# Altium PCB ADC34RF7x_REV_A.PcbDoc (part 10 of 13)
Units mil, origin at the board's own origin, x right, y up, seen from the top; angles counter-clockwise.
Board outline 6250 x 2716.54 mil, 18 copper layers (Top Layer, L2 GND, L3 PWR, L4 GND, L5 PWR/SIG, L6 GND, L7 SIGNAL, L8 GND, L9 GND, L10 SIGNAL, L11 GND, L12 SIGNAL, L13 GND, L14 PWR, L15 GND, L16 PWR/SIG, L16 GND, Bottom Layer), stack 95.314 mil thick; 668 components, 786 nets, 3150 pads, 2020 vias.
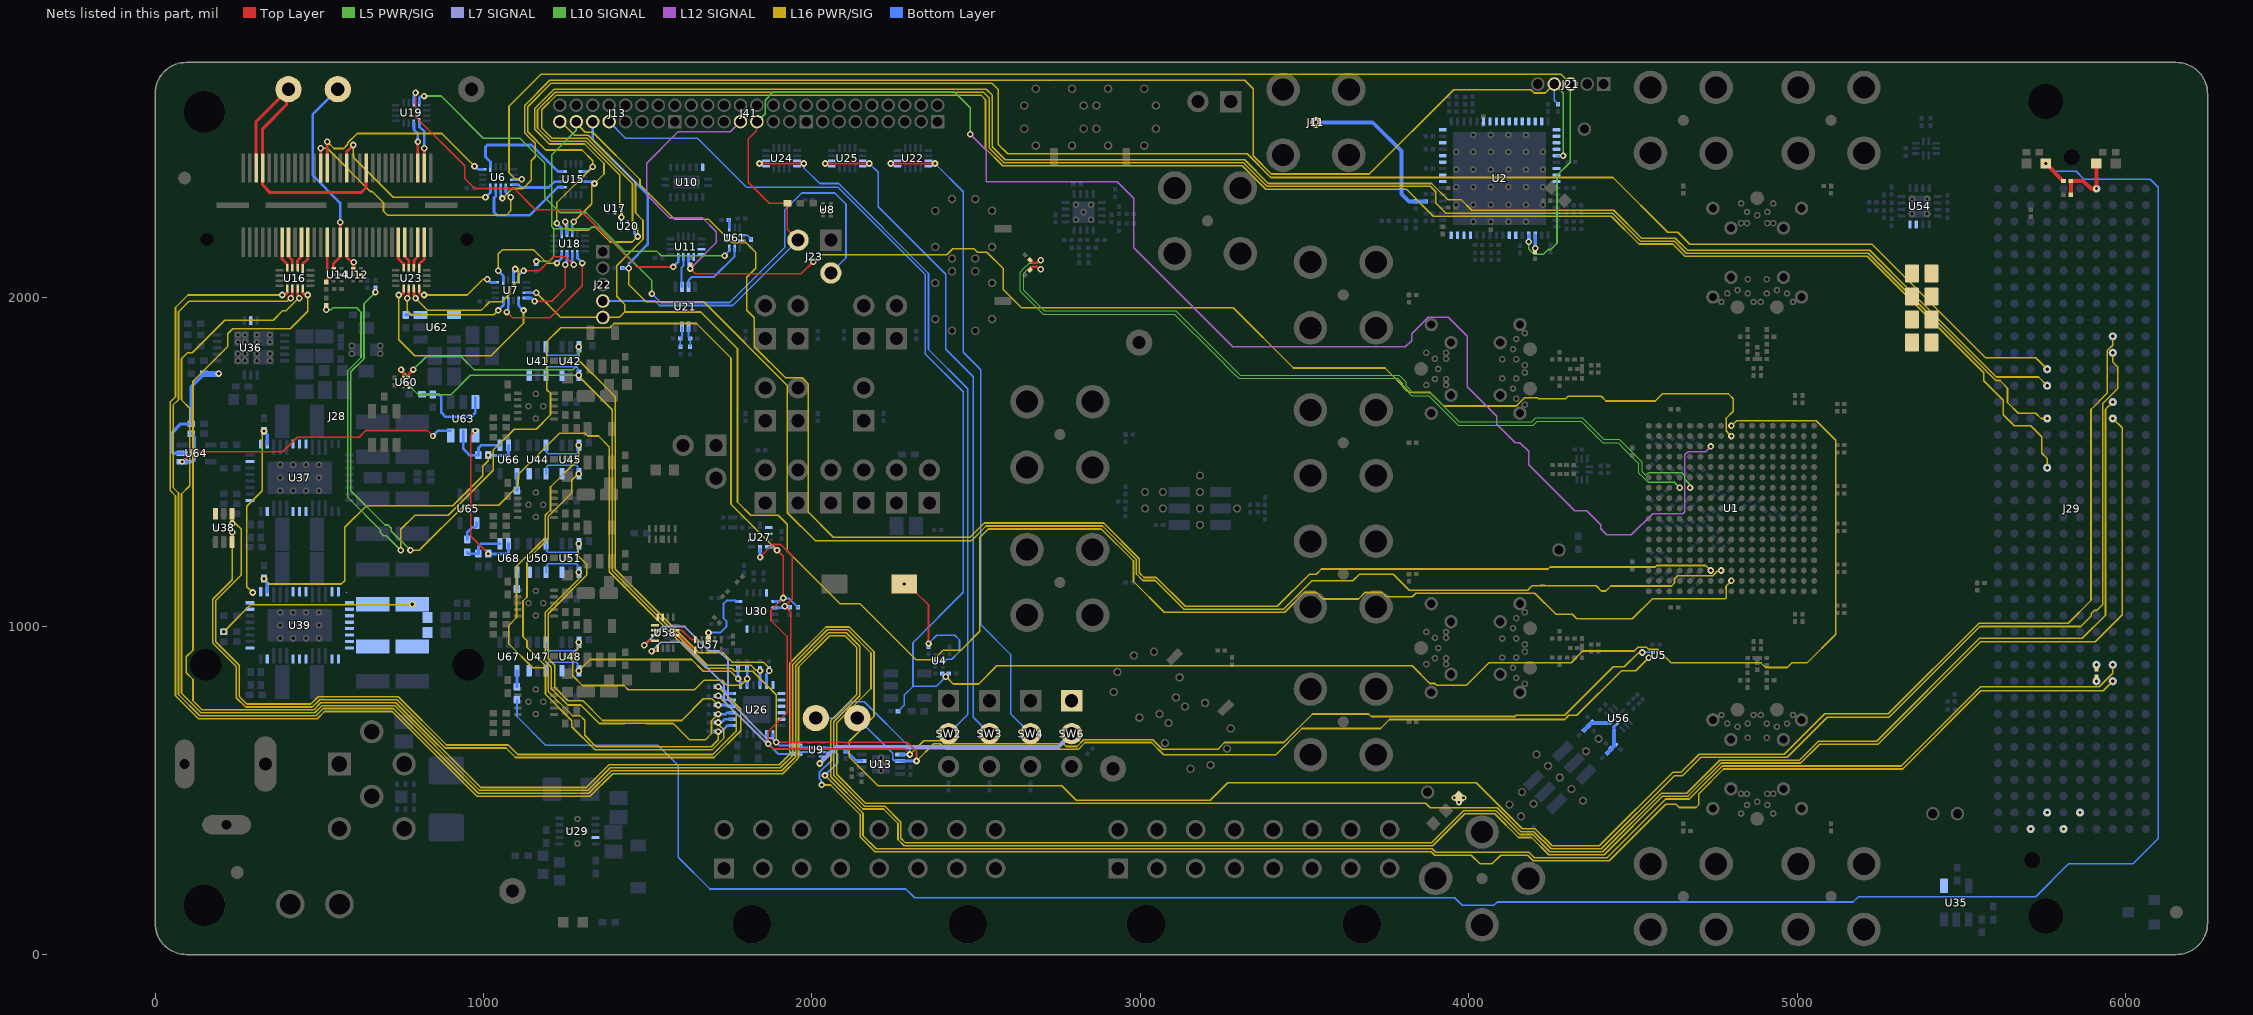
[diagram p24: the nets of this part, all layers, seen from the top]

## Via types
v1: diameter 20, hole 10, Top Layer to Bottom Layer, tented both sides, 1793 vias
v2: diameter 24, hole 12, Top Layer to Bottom Layer, tented both sides, 168 vias
v3: diameter 18, hole 8, Top Layer to Bottom Layer, tented both sides, 59 vias

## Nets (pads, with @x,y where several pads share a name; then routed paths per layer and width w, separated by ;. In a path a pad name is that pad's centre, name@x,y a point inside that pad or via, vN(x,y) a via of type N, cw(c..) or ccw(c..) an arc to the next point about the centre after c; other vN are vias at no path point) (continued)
NetR211_2: R211.2 R214.1 U13.3 | length 61.5
  Bottom Layer w8: R211.2@2102.45,618.97 2102.45,618.18 2104.75,615.88 2109.84,615.88 2134.45,591.28 2149.34,591.28 U13.3@2151.24,589.37
NetR216_2: R216.2 U61.8 | length 25
  Bottom Layer w8: R216.2@1746.72,2236.55 1748.72,2236.55 U61.8@1748.72,2213.57
NetR220_1: R220.1
NetR220_2: R220.2
NetR221_1: R221.1
NetR221_2: R221.2
NetR222_1: R222.1
NetR222_2: R222.2
NetR223_1: R223.1
NetR223_2: R223.2
NetR224_1: R224.1 R226.2 U63.3 | length 270.9
  Bottom Layer w8: R224.1@812.97,1705.75 845.79,1705.75 R226.2@845.87,1705.66 863.16,1705.66 871.42,1697.4 871.42,1650.53 884.64,1637.31 962.7,1637.31 975.39,1649.99 U63.3@975.39,1682.4 U63.3@975.39,1697.4
NetR225_2: R225.2 U62.3 | length 45
  Bottom Layer w8: R225.2@763.07,1947.7 U62.3@808.07,1947.7
NetR229_1: R229.1 U65.4 | length 67.2
  Bottom Layer w8: R229.1@950.16,1264.12 950.16,1284.67 966.78,1301.3 975.61,1301.3 979.49,1305.17 U65.4@979.49,1314
NetR230_1: R230.1 U66.4 | length 51
  Bottom Layer w8: R230.1@1101.81,1412.9 U66.4@1101.81,1463.86
NetR233_1: R233.1 U67.4 | length 48.6
  Bottom Layer w8: R233.1@1101.81,815.28 U67.4@1101.81,863.86
NetR234_1: R234.1 U68.4 | length 51
  Bottom Layer w8: R234.1@1101.81,1112.9 U68.4@1101.81,1163.86
NetSW2_1: SW2.1 U24.5 U24.6 U24.15 U24.16 | length 2135.7
  Top Layer w5: v1(1840.38,2408.82) v1(1974.87,2408.82)
  Bottom Layer w5: v1(1974.87,2408.82) 1976.04,2407.65 1976.04,2395.23 2023.51,2347.76 2081.35,2347.76 2355.19,2073.92 2355.19,1842.33 2473.15,1724.37 cw(c2469.6,1720.85) 2474.6,1720.85 2474.6,731.11 SW2.1@2416.03,672.55
NetSW3_1: SW3.1 U25.5 U25.6 U25.15 U25.16 | length 2022.4
  Top Layer w5: v1(2040.38,2408.82) v1(2174.87,2408.82)
  Bottom Layer w5: v1(2174.87,2408.82) 2202,2381.68 2202,2276.77 2407.21,2071.55 2407.21,1843 2491,1759.21 2491,722.58 SW3.1@2541.03,672.55
NetSW4_1: SW4.1 U22.5 U22.6 U22.15 U22.16 | length 1990.9
  Top Layer w5: v1(2240.38,2408.82) v1(2374.87,2408.82)
  Bottom Layer w5: v1(2374.87,2408.82) 2461,2322.69 2461,1834 2512.38,1782.62 cw(c2508.84,1779.09) 2513.84,1779.09 2513.84,1364.21 2513.84,1007 ccw(c2518.84,1007) 2515.29,1003.48 ; 2515.31,1003.46 2605,913.77 2605,733.58 SW4.1@2666.03,672.55
NetSW6_1: SW6.1 U9.8 | length 828.8
  L7 SIGNAL w13: v1(2023.74,581.72) 2073.23,631.2 2749.69,631.2 SW6.1@2791.03,672.55
  Bottom Layer w6: v1(2023.74,581.72) 2023.74,584.72 2030.85,591.83 U9.8@2030.85,602.63
NetU2_1: U2.1
NetU2_2: U2.2
NetU2_3: U2.3
NetU2_4: U2.4
NetU2_7: U2.7
NetU2_8: U2.8
NetU2_9: U2.9
NetU2_22: U2.22
NetU2_23: U2.23
NetU2_29: U2.29
NetU2_30: U2.30
NetU2_31: U2.31
NetU2_32: U2.32
NetU2_40: U2.40
NetU2_41: U2.41
NetU2_43: U2.43
NetU2_44: U2.44
NetU2_46: U2.46
NetU2_48: U2.48
NetU2_54: U2.54
NetU2_55: U2.55
NetU2_56: U2.56
NetU2_57: U2.57
NetU2_58: U2.58
NetU2_59: U2.59
NetU2_60: U2.60
NetU2_61: U2.61
NetU2_62: U2.62
NetU2_63: U2.63
NetU4_5: U4.5
NetU5_C2: U5.C2
NetU8_5: U8.5
NetU10_7: U10.7
NetU11_7: U11.7
NetU11_8: U11.8
NetU11_9: U11.9
NetU12_5: U12.5
NetU14_5: U14.5
NetU17_5: U17.5
NetU20_5: U20.5
NetU26_12: U26.12
NetU26_13: U26.13
NetU26_14: U26.14
NetU26_15: U26.15
NetU26_16: U26.16
NetU26_17: U26.17
NetU27_2: U27.2
NetU27_6: U27.6
NetU27_7: U27.7
NetU29_9: U29.9
NetU30_4: U30.4
NetU30_12: U30.12
NetU35_4: U35.4
NetU36_4: U36.4
NetU37_2: U37.2
NetU37_7: U37.7
NetU37_8: U37.8
NetU37_9: U37.9
NetU37_30: U37.30
NetU37_31: U37.31
NetU37_32: U37.32
NetU37_36: U37.36
NetU37_39: U37.39
NetU37_45: U37.45
NetU38_6: U38.6
NetU39_2: U39.2
NetU39_7: U39.7
NetU39_8: U39.8
NetU39_9: U39.9
NetU39_30: U39.30
NetU39_31: U39.31
NetU39_32: U39.32
NetU39_36: U39.36
NetU39_39: U39.39
NetU39_45: U39.45
NetU41_6: U41.6
NetU42_6: U42.6
NetU44_6: U44.6
NetU45_6: U45.6
NetU47_6: U47.6
NetU48_6: U48.6
NetU50_6: U50.6
NetU51_6: U51.6
NetU54_3: U54.3
NetU54_4: U54.4
NetU58_7: U58.7
NetU58_8: U58.8
NetU58_9: U58.9
NetU58_10: U58.10
NetU58_11: U58.11
NetU60_C2: U60.C2
NetU61_2: U61.2
NetU61_6: U61.6
NetU61_7: U61.7
NetU62_4: U62.4
PDN_ADC_FMC_GPIOVDD: U11.11 U21.6 | length 93
  Bottom Layer w6: U21.6@1604.5,2033.16 1603.5,2034.15 1603.5,2091.91 1608.5,2096.91 U11.11@1608.5,2123.66
PDN_ADC_FMC_VADJ: R218.1 R238.1 U21.3 | length 63.4
  Bottom Layer w5: R238.1@1599.89,1850.36 1599.5,1850.76 R218.1@1599.5,1875.36 1600.29,1875.36 1604.5,1879.58 U21.3@1604.5,1911.11
PDN_ADC_FT: J28.5 U19.2 | length 143.1
  Top Layer w8: J28.5@800.29,2395 v1(800.29,2475)
  Bottom Layer w8: U19.2@788.15,2533.03 788.15,2511.41 799.88,2499.69 799.88,2475.41 v1(800.29,2475)
PDN_ADC_GPIOVDD: J41.9 R50.1 U1.J2 U11.10 | length 4493.5
  Top Layer w5: R50.1@1630.62,2100.47 1629.94,2099.79 1629.94,2089.35 v1(1629.25,2088.66) 1645.09,2072.82 1966.81,2072.82 v1(2003.76,2109.77)
  L16 PWR/SIG w4: 4783.55,1632.27 4783.55,1595.19 4792.25,1586.49
  L16 PWR/SIG w5: v1(2003.76,2109.77) 2024.87,2130.88 2410.75,2130.88 2429.3,2149.42 2493.35,2149.42 2504.08,2138.7 2532.87,2138.7 2582.33,2089.25 2582.33,2025.14 2638.27,1969.2 3283.13,1969.2 3466.23,1786.11 3745.24,1786.11 3818.85,1712.5 3881.3,1712.5 3923.63,1670.17 4145.09,1670.17 4169.89,1694.97 4209.63,1694.97 4212.69,1691.91 4294.61,1691.91 4302.56,1699.85 4403.71,1699.85 4417.96,1685.6 4568.06,1685.6 4589.53,1707.07 4791.13,1707.07 4805.92,1692.27 4805.92,1654.65 4783.55,1632.27 ; 4792.25,1586.49 v1(4800,1578.74)
  L12 SIGNAL w5: v1(1629.25,2088.66) 1708.55,2167.96 1708.55,2200.88 1666.74,2242.69 1567.3,2242.69 1496.77,2313.22 1496.77,2409.64 1592.13,2505 1751.56,2505 J41.9@1782.62,2536.06
  Bottom Layer w8: v1@1624.25,2096.91 U11.10@1624.25,2123.66
PDN_ADC_USB_GPIOVDD: U11.12 U19.11 | length 1137.7
  Top Layer w5: v1(793.15,2624.06) 793.15,2551.14 942.82,2401.47 942.82,2363.28 973.39,2332.72 1093.23,2332.72 1157.9,2268.05 1292.9,2268.05 1467.29,2093.66 v1(1577.76,2093.66)
  Bottom Layer w8: U19.11@788.15,2594.06 788.15,2615.81 793.15,2620.81 v1(793.15,2624.06) ; v1(1577.76,2093.66) 1592.76,2108.66 U11.12@1592.76,2123.66
PG-3p3V_Util: R112.1 R228.1 U36.19 U64.2 | length 376.3
  Bottom Layer w10: U64.2@82.39,1526.18 55.93,1526.18 50.08,1532.04 50.08,1587.83 78,1615.76 R228.1@109.72,1615.76 109.72,1728.58 142.28,1761.14 142.28,1763.11 147.12,1767.95 R112.1@149.09,1767.95
  Bottom Layer w18: R112.1@149.09,1767.95 191.86,1767.95 192.98,1769.07 v1(193.52,1769.07)
PG-DVDD09: R118.2 U37.3 U39.1 U39.46 | length 565.1
  L16 PWR/SIG w5: v1(297.23,1102.28) 279.29,1120.22 279.29,1365.17 326.53,1412.4 326.53,1589.13 v1(331.53,1594.13)
  Bottom Layer w10: v1(331.53,1594.13) 331.53,1592.17 341.53,1582.17 U37.3@341.53,1554.13
PG-FPGA: D1.1 J29.D1 R85.1 R199.2 | length 206.2
  Top Layer w12: R85.1@5833.47,2313.53 R199.2@5833.47,2355.76 5871.1,2355.76 5894.59,2332.27 v1(5911.42,2332.27) D1.1@5911.42,2408.52
PG-M2C: D2.1 R199.1 R233.2 | length 7966.6
  Top Layer w12: v1(5757.42,2408.51) 5809.87,2356.06 5811.12,2356.06 R199.1@5811.42,2355.76
  Bottom Layer w5: R233.2@1101.81,775.91 1101.81,724.58 1189.66,636.72 1532.05,636.72 1592.96,575.82 1592.96,296.15 1689.55,199.56 2286.04,199.56 2312.91,172.69 3957.22,172.69 3979.91,150 4076.79,150 4086.62,159.83 5170.35,159.83 5186.85,176.33 5726.74,176.33 5826.74,276.33 6022.93,276.33 6100,353.4 6100,2335.96 6075,2360.96 5873.69,2360.96 5849.65,2385 5780.93,2385 v1(5757.42,2408.51)
PG-switcher: R125.2 R232.1 U39.3 U66.2 | length 1109
  L16 PWR/SIG w5: v1(331.53,1144.64) 347.87,1128.3 567.09,1128.3 577.36,1138.57 577.36,1300.69 643.48,1366.8 906.64,1366.8 997.58,1457.74 997.58,1486.36 1014.58,1503.36 v3(1014.58,1520.81)
  Bottom Layer w8: v3(1014.58,1520.81) 1015.96,1519.43 1071.53,1519.43 1076.22,1524.12 U66.2@1076.22,1550.47
  Bottom Layer w10: v1(331.53,1144.64) 331.53,1142.67 341.53,1132.67 U39.3@341.53,1104.64
PG-VDD12: R229.2 R235.1 U68.1 | length 127.3
  Bottom Layer w8: R229.2@950.16,1224.75 954.09,1220.81 R235.1@984.58,1220.81 984.58,1242.86 992.19,1250.47 U68.1@1050.63,1250.47
RPI_LOAD_FT: J28.21 J28.53 J28.55 TP3.1 | length 986.2
  Top Layer w9: J28.55@307.83,2395 307.83,2536.57 399.53,2628.27 399.53,2586.77 327.52,2514.76 J28.53@327.52,2395 327.52,2343.14 350.66,2320 627.05,2320 642.48,2335.43 J28.21@642.48,2395
  Bottom Layer w9: TP3.1@406.26,2635 TP3.1@412.99,2628.27
RSTb_ADC_FMC_GPIOVDD: U21.7 U61.4 | length 215
  Bottom Layer w6: U21.7@1624.18,2033.16 1624.18,2053.16 1634.18,2063.16 1701.63,2063.16 1764.47,2126 U61.4@1764.47,2150.58
RSTb_ADC_FMC_VADJ: R217.1 R237.1 U21.2 | length 63.3
  Bottom Layer w5: U21.2@1624.18,1911.11 1624.18,1879.58 1628.4,1875.36 R217.1@1629.18,1875.36 R237.1@1629.18,1850.36
RSTb_ADC_FT: J28.3 U19.1 | length 144.6
  Top Layer w8: J28.3@819.65,2395 v1(819.65,2455)
  Bottom Layer w8: U19.1@803.9,2533.03 803.9,2521.73 819.56,2506.07 819.56,2455.08 v1(819.65,2455)
RSTb_ADC_GPIOVDD: R219.1 U61.1 | length 34.5
  Bottom Layer w5: U61.1@1786.12,2189.95 1802.97,2189.95 1814.87,2178.05 R219.1@1814.87,2177.26
RSTb_ADC_PIN: J13.9 R45.2 R48.2 R49.2 U1.J1 | length 6578.5
  L16 PWR/SIG w5: v1(2407.21,845.43) 2409.21,845.43 2430.7,823.95 2507.95,823.95 2562.95,878.95 3828.03,878.95 3881.69,825.29 3897.29,825.29 3902.33,820.25 3993.54,820.25 4062.08,888.79 4312.1,888.79 4347.51,924.21 4504.55,924.21 4516.51,936.17 4540.91,936.17 4548.28,928.79 4576.37,928.79 4617.22,887.93 4890.21,887.93 4904.26,873.88 4969.72,873.88 4983.78,887.93 5030.42,887.93 5117.86,975.37 5117.86,1566.27 5058.39,1625.74 4815.5,1625.74 v1(4800,1610.24)
  Bottom Layer w5: J13.9@1382.61,2536.06 1432.61,2486.06 1651.56,2486.06 1800.81,2336.81 2079.57,2336.81 2345.62,2070.76 2345.62,1828.82 2461,1713.44 2461,1104.69 cw(c2456,1104.69) 2459.54,1101.16 2307.67,949.29 2307.67,816.41 ; R49.2@2262.05,740.77 2262.83,740.77 2266.63,744.57 2266.63,745.36 2281.3,760.02 2281.3,790.04 2307.67,816.41 ; R45.2@2397.21,855.43 2398,855.43 v1@2407.21,846.22 ; R48.2@2417.21,855.43 2416.43,855.43 v1@2407.21,846.22 ; 2307.67,816.41 2378.19,816.41 v1(2407.21,845.43) v1@2407.21,846.22
RSTb_ADC_USB_GPIOVDD: U19.12 U61.5 | length 1238.4
  L5 PWR/SIG w5: v1(818.9,2614.06) 870.98,2614.06 998.98,2486.06 1110.9,2486.06 1186.49,2410.47 1186.49,2305.08 1231.86,2259.71 1311.94,2259.71 1429.61,2142.04 1526.79,2142.04 1540.78,2128.05 v1(1734.06,2128.05)
  Bottom Layer w6: v1(1734.06,2128.05) 1748.72,2142.7 U61.5@1748.72,2150.58
  Bottom Layer w8: U19.12@803.9,2594.06 803.9,2608.2 807.46,2611.76 816.6,2611.76 v1(818.9,2614.06)
RSTb_MANUAL: R47.2 SW1.2 U4.2 | length 435.3
  Top Layer w5: v1(2281.3,1128.15) 2291.39,1128.15 2318.41,1101.12 2318.76,1101.12 2355.17,1064.72 v1(2355.17,946.85)
  Bottom Layer w5: v1(2355.17,946.85) 2380.31,972 2435.02,972 2449.26,957.76 2449.26,922.49 2425.95,899.18 2411.27,899.18 2407.21,895.12 U4.2@2398.98,895.12
  Bottom Layer w8: R47.2@2355.16,936.85 v1(2355.17,946.85)
SCL: R66.1 R68.1 R69.1 TP6.1 U5.A2 U13.6 U26.19 U27.10 U30.14 U58.12 | length 7571.7
  Top Layer w5: v1(1489.25,942.05) 1503.16,955.97 U58.12@1522.09,955.97 ; v1(1842.14,1209.98) 1880.83,1248.68 1905.26,1248.68 1940,1213.95 1940,1083.45 v1(1917.4,1060.85) 1935.86,1042.39 1935.86,646.2 ; v1(1891.49,646.2) 1935.86,646.2 ; v1(2318.5,589.37) 2318.5,618.37 2290.66,646.2 1935.86,646.2
  L16 PWR/SIG w5: v1(777.51,1230.71) 804.28,1230.71 941.91,1368.34 1045.98,1368.34 1105.06,1427.42 1105.06,1460.93 1231.44,1587.31 1242.63,1587.31 1242.96,1586.97 1309.82,1586.97 1317.9,1578.89 1350.09,1578.89 1383.34,1545.63 1383.34,1165.46 1677.37,871.43 1756.1,871.43 1765.1,862.43 1820.09,862.43 1891.49,791.03 v1(1891.49,646.2) ; v1(2318.5,589.37) 2370.99,641.87 2390.85,641.87 2408.15,624.57 2810.91,624.57 2831.77,645.43 3034.4,645.43 3071.15,608.69 3412.98,608.69 3492.6,688.31 3731.4,688.31 3758.92,715.83 4292.59,715.83 4304.93,728.17 4329.5,728.17 4465.33,864 4508.58,864 v1(4548.13,903.54)
  L5 PWR/SIG w5: v1(670.87,2016.47) 636.05,1981.65 636.05,1814.32 596.14,1774.41 596.14,1412.08 700.22,1308 709.5,1308 719.17,1298.33 719.17,1289.05 v1(777.51,1230.71)
  L7 SIGNAL w6: v1(1489.25,942.05) 1545.4,998.21 1612.98,998.21 1687.55,923.63 1716.71,923.63 1744.97,895.37 1744.97,775.83 1861.59,659.22 1878.48,659.22 v1(1891.49,646.2)
  Bottom Layer w5: v1(670.87,2016.47) R68.1@670.87,2030.47 ; v1(1917.4,1060.85) 1919.31,1058.94 1930.49,1058.94 R66.1@1932.4,1057.03 ; TP6.1@2138.29,719.94 2245.81,612.41 2245.81,594.59 2249.65,590.76 2267.11,590.76 U13.6@2268.5,589.37 ; v1(4548.13,903.54) U5.A2@4563.13,903.54
  Bottom Layer w6: U26.19@1881.49,671.2 1881.58,671.12 1881.58,657.12 1891.49,647.2 v1(1891.49,646.2) 1892.01,646.2 1902.01,636.2 R69.1@1941.49,636.2
  Bottom Layer w8: v1(1842.14,1209.98) U27.10@1842.14,1234.98 ; U13.6@2268.5,589.37 v1(2318.5,589.37)
  Bottom Layer w9: U30.14@1887.4,1055.85 1887.48,1055.94 1909.51,1055.94 1914.42,1060.85 v1(1917.4,1060.85)
SCL0: R93.1 U26.2 U44.3 U45.3 | length 1794.1
  L16 PWR/SIG w5: v1(1290.31,1550.47) 1290.31,1509.76 1204.05,1423.49 1204.05,1353.58 1188.03,1337.56 1188.03,1269.42 1100.6,1182 1100.6,1026.05 1077.35,1002.8 1077.35,945.63 1149.77,873.21 1182.4,873.21 1188.59,867.02 1188.59,792.73 1269.11,712.21 1269.11,693.7 1338.81,624 1697.05,624 1731.06,658.01 1731.06,685.64 1719.76,696.95 1719.76,697.24 1714.56,702.44 v1(1714.56,706.5)
  Bottom Layer w5: U44.3@1190.31,1550.47 1190.65,1550.14 1190.65,1531.08 1196.95,1524.77 1283.07,1524.77 1287.02,1528.72 1287.02,1547.18 v1(1290.31,1550.47)
  Bottom Layer w8: v1(1714.56,706.5) 1714.83,706.76 1725.18,706.76 1734.9,716.48 U26.2@1757.48,716.48
SCL1: R95.1 U26.4 U50.3 U51.3 | length 1267.7
  L16 PWR/SIG w5: v1(1290.31,1250.47) 1288.22,1248.38 1288.22,1213.61 1313.9,1187.93 1313.9,1154.62 1197.03,1037.75 1197.03,900.86 1216.6,881.3 1216.6,813.39 1256.7,773.28 1301.85,773.28 1362.39,712.73 1499.4,712.73 1499.47,712.66 1603.59,712.66 1669.56,778.63 1695.8,778.63 v1(1714.56,759.87)
  Bottom Layer w5: U50.3@1190.31,1250.47 1190.65,1250.14 1190.65,1231.08 1196.95,1224.77 1283.07,1224.77 1287.02,1228.72 1287.02,1247.18 v1(1290.31,1250.47)
  Bottom Layer w8: v1(1714.56,759.87) 1737.49,759.87 1741.51,755.85 U26.4@1757.48,755.85
SCL2: R97.1 U26.6 U38.3 | length 2471.8
  Top Layer w10: U38.3@234.6,1255.95 v1(234.6,1285.95)
  L16 PWR/SIG w5: v1(234.6,1285.95) 234.6,1140.75 175.65,1081.8 175.65,948.83 247.45,877.03 247.45,781.92 275.57,753.8 478.89,753.8 501.09,776 736.74,776 883.78,628.95 1068.59,628.95 1097.55,600 1701.78,600 1783.07,681.29 1783.07,746.73 v1(1714.56,815.24)
  Bottom Layer w8: R97.1@1707.48,815.22 1714.55,815.22 1716.86,812.94 1724.17,812.94 1741.51,795.6 1757.1,795.6 U26.6@1757.48,795.22
SCL3: R99.1 U26.8 U47.3 U48.3 | length 877.8
  L16 PWR/SIG w5: v1(1290.31,950.47) 1290.31,935.4 1271.73,916.82 1271.73,848.82 1301.34,819.21 1427.86,819.21 1441.07,806 1642.4,806 1671.55,835.15 1726.56,835.15 1741.6,820.11 1783.15,820.11 v1(1802.77,839.72)
  Bottom Layer w5: U47.3@1190.31,950.47 1190.65,950.14 1190.65,931.08 1196.95,924.77 1283.07,924.77 1287.02,928.72 1287.02,947.18 v1(1290.31,950.47)
  Bottom Layer w8: U26.8@1802.75,820.81 v1(1802.77,839.72) R99.1@1802.75,870.81
SCL4: R101.1 U26.11 U41.3 U42.3 U60.A2 | length 2153.8
  Top Layer w8: U60.A2@772.4,1757.72 772.4,1767.26 v1(786.3,1781.16)
  L16 PWR/SIG w5: v1(1290.31,1850.47) 1290.31,1809.86 1377.37,1722.81 1401.34,1698.83 1401.34,1173.37 1452.36,1122.36 1452.36,1122.27 1462.02,1112.61 1462.11,1112.61 1655.89,918.82 1729.02,918.82 1757.4,890.45 1851.78,890.45 1866.95,875.27 1866.95,866.59 v1(1869.82,863.72)
  L10 SIGNAL w5: v1(786.3,1781.16) 825.54,1820.4 932.02,1820.4 971.26,1781.16 1273.51,1781.16 1290.31,1797.96 v1(1290.31,1850.47)
  Bottom Layer w5: U41.3@1190.31,1850.47 1190.65,1850.14 1190.65,1831.08 1196.95,1824.77 1283.07,1824.77 1287.02,1828.72 1287.02,1847.18 v1(1290.31,1850.47)
  Bottom Layer w8: U26.11@1861.81,820.81 1861.81,853.04 1869.79,861.02 v1(1869.82,863.72) ; v1(1869.82,863.72) R101.1@1869.81,870.81 v1(1869.82,863.72)
SCL_FMC: J29.C30 U9.6 | length 4458.8
  L16 PWR/SIG w5: v1(2039.93,545.38) 2040.44,545.38 2155.68,430.14 2155.68,361.87 2195.75,321.8 3889.45,321.8 3899.91,311.34 4183.72,311.34 4200.29,294.77 4421.05,294.77 4599.69,473.4 4671.75,473.4 4772.34,574 5317.34,574 5558.34,815 5920,815 5961.42,856.42 v1(5961.42,882.27)
  Bottom Layer w6: U9.6@2030.85,630.18 2057.16,630.18 2077.43,609.92 2077.43,582.88 v1(2039.93,545.38)
SCL_FMC_3p3V: R69.2 U9.3 | length 34.4
  Bottom Layer w6: R69.2@1963.54,636.2 1964.33,636.2 1970.35,630.18 U9.3@1995.42,630.18
SCLK_ADC: J13.11 R59.2 U1.K15 | length 4745.3
  L16 PWR/SIG w4: 4626.77,1143.97 4627.48,1143.97 4636.31,1152.8 4743.22,1152.8 4756.8,1166.37 4765.58,1166.37 v1(4768.5,1169.29)
  L16 PWR/SIG w5: v1(1442.36,2090.01) 1442.36,2040.01 1494.72,1987.66 1670.26,1987.66 1925.28,1732.64 1925.28,1345.57 2011.37,1259.47 2484.92,1259.47 2530.33,1304.89 2885.16,1304.89 2988.17,1201.88 2988.17,1158.54 3007.65,1139.05 3045.26,1139.05 3133.02,1051.29 3436.16,1051.29 3522.66,1137.8 3646.77,1137.8 3667.27,1158.29 3770.03,1158.29 3819.04,1109.28 4179.75,1109.28 4193.01,1122.54 4216.83,1122.54 4217.83,1123.54 4231.5,1123.54 4232.5,1122.54 4388.3,1122.54 4404.07,1106.77 4417.74,1106.77 4433.26,1122.3 4617.44,1122.3 4626.77,1131.62 4626.77,1143.97
  Bottom Layer w8: J13.11@1332.61,2536.06 1332.61,2481.88 1500,2314.49 1500,2162.17 1442.36,2104.53 v1(1442.36,2090.01) R59.2@1422.36,2090.01
SCLK_ADC_FMC_GPIOVDD: U7.1 U18.12 | length 324.6
  L16 PWR/SIG w5: v1(1044.74,2082.4) 1044.74,2133.5 1057.61,2146.38 1152.16,2146.38 1193.06,2105.47 v1(1223.52,2105.47)
  Bottom Layer w8: v1(1044.74,2082.4) 1059.74,2067.4 U7.1@1059.74,2052.4 ; v1(1223.52,2105.47) 1238.52,2120.47 U18.12@1238.52,2135.47
SCLK_ADC_FT: J28.4@819.65,2169.41 U23.1 | length 84.6
  Top Layer w8: U23.1@803.9,2091.38 803.9,2102.68 819.56,2118.34 819.56,2169.33 J28.4@819.65,2169.41
SCLK_ADC_USB_GPIOVDD: U7.16 U23.12 | length 273.3
  Top Layer w8: U23.12@803.9,2028.39 803.9,2014.24 807.46,2010.68 816.6,2010.68 v1(818.9,2008.39)
  L16 PWR/SIG w5: v1(818.9,2008.39) 950.35,2008.39 998.46,2056.5 v1(1011.12,2056.5)
  Bottom Layer w8: v1(1011.12,2056.5) 1011.9,2056.5 1014.2,2054.2 1014.2,2053.41 1021.12,2046.5 U7.16@1036.12,2046.5
SCLK_FMC_VADJ: J29.G12 U15.1 U18.1 | length 5735.3
  L16 PWR/SIG w5: v1(1223.52,2226.5) 1223.52,2289.88 v1(1332.89,2399.25) 1332.89,2417.13 1300.01,2450 1189.85,2450 1134.3,2505.55 1134.3,2581.57 1205.76,2653.04 2548.47,2653.04 2566.97,2634.54 2566.97,2467.09 2596.06,2438 3325.25,2438 3397.25,2366 4439.68,2366 4606.2,2199.47 4636.73,2199.47 4673.53,2162.67 5228.33,2162.67 5574,1817 5604.77,1817 5605,1816.77 5667.84,1816.77 5668.07,1817 5726.69,1817 v1(5761.42,1782.27)
  Bottom Layer w8: v1(1223.52,2226.5) 1238.52,2211.5 U18.1@1238.52,2196.5 ; U15.1@1302.89,2384.25 1317.89,2384.25 v1(1332.89,2399.25)
SCLK_FPGA_FT: J28.40 U16.1 | length 84.6
  Top Layer w8: U16.1@449.49,2091.46 449.49,2102.76 465.15,2118.43 465.15,2169.41 J28.40@465.23,2169.49
SCLK_FPGA_VADJ: J29.C10 U16.12 | length 9558.8
  Top Layer w8: U16.12@449.57,2028.39 449.57,2014.24 453.13,2010.68 462.27,2010.68 v1(464.57,2008.39)
  L16 PWR/SIG w5: v1(464.57,2008.39) 464.57,1958.39 411.64,1905.46 236.49,1905.46 221.26,1890.22 221.26,1851.26 115.39,1745.39 115.39,926.75 95.17,906.53 95.17,857.88 115.39,837.66 115.39,772.83 143.42,744.8 482.62,744.8 504.82,767 733.01,767 991.29,508.72 1313.26,508.72 1382.39,577.84 1900.26,577.84 1932.36,609.95 1932.36,886.76 2043.07,997.47 2113.41,997.47 2189.09,921.8 2189.09,725.17 2113.7,649.78 2113.7,601.19 2201.35,513.54 2761.03,513.54 2804.58,470 3213.25,470 3266.29,523.04 4022.93,523.04 4162.71,383.26 4202.19,383.26 4254.68,330.77 4397.83,330.77 4622.07,555 4646.75,555 4701.75,610 4960.89,610 5083.77,732.88 5277.38,732.88 5553.68,1009.18 5825.91,1009.18 5895,1078.27 5895,1659.8 5944.92,1709.72 5944.92,1839.1 5961.42,1855.6 v1(5961.42,1882.27)
SCLK_LMK: R53.1 U2.19 | length 50
  Top Layer w10: R53.1@4202.45,2140.43 v1(4202.45,2150.43)
  Bottom Layer w10: v1(4202.45,2150.43) U2.19@4202.45,2190.43
SCLK_LMK_FMC_3p3V: U6.1 U15.12 | length 338.4
  Bottom Layer w8: U6.1@1021.12,2398.62 1021.12,2413.62 1006.12,2428.62 1006.12,2459.21 1011.9,2465 1146.12,2465 1226.86,2384.25 U15.12@1241.86,2384.25
SCLK_LMK_USB: J28.33 U6.16 | length 629.4
  Top Layer w8: J28.33@524.05,2395 v1(524.05,2475)
  L16 PWR/SIG w5: v1(524.05,2475) 544.63,2454.42 574.42,2454.42 586.93,2466.93 586.93,2471.83 615.09,2500 873.24,2500 v1(972.49,2400.75)
  Bottom Layer w8: v1(972.49,2400.75) 973.28,2400.75 975.58,2398.45 975.58,2397.66 982.49,2390.75 U6.16@997.49,2390.75
SDA: R67.1 R185.1 R186.1 TP7.1 U5.A1 U13.5 U26.20 U27.9 U30.13 U58.13 | length 7880.2
  Top Layer w5: v1(1893.71,1231.38) 1912.4,1212.7 v1(1912.4,1085.54) 1875.63,1048.77 1875.63,1017.13 1924.45,968.31 1924.45,736.6 1866.81,678.96 v1(1866.81,641.2) 1882.39,625.62 2281.93,625.62 v1(2298.5,609.06)
  Top Layer w6: v1(1511.82,923.63) 1512.26,924.08 1529.03,924.08 1529.96,925.01 U58.13@1529.96,932.35
  Top Layer w9: v1(521.32,1962.99) R185.1@521.32,1976.99
  L16 PWR/SIG w5: v1(747.83,1230.71) 747.83,1294.63 791.17,1337.98 892.66,1337.98 959.57,1404.89 1020.62,1465.94 1021,1465.94 1030.08,1475.02 1030.08,1536.29 1093.7,1599.92 1160.23,1599.92 1203.8,1643.49 1203.8,1709.12 1192.98,1719.94 1192.98,1866.49 1235.2,1908.71 1384.69,1908.71 1397.39,1921.41 1648.49,1921.41 1753.69,1816.22 1753.69,1371.41 v1(1893.71,1231.38) ; v1(2298.5,609.06) 2340.31,650.87 2394.58,650.87 2403.4,642.05 2766.41,642.05 2774.89,633.57 2807.18,633.57 2828.05,654.43 3038.12,654.43 3067.17,625.39 3236.43,625.39 3256.47,645.43 3437,645.43 3524.08,732.51 3695.06,732.51 3702.74,724.83 4140.94,724.83 4144.28,728.17 4292.2,728.17 4440.08,876.05 4474.08,876.05 4515.73,917.7 4526.54,917.7 v1(4528.51,919.67)
  L5 PWR/SIG w5: v1(521.32,1962.99) 521.37,1963.05 535.89,1963.05 541.86,1969.02 613.54,1969.02 627.05,1955.51 627.05,1818.05 587.14,1778.14 587.14,1391.4 686.17,1292.37 686.17,1284.66 695.83,1275 703.54,1275 v1(747.83,1230.71)
  L7 SIGNAL w6: v1(1511.82,923.63) 1539.08,950.89 1604.1,950.89 1732.9,822.08 1732.9,771.52 1863.22,641.2 v1(1866.81,641.2)
  Bottom Layer w5: U26.20@1861.81,671.2 1861.81,650.26 1866.81,645.26 v1(1866.81,641.2) ; TP7.1@2011.8,719.94 2069.3,719.94 2118.94,769.59 2159.06,769.59 2298.5,630.15 v1(2298.5,609.06) ; v1@4528.13,919.29 v1(4528.51,919.67) 4528.88,920.04 4554.96,920.04 4555.72,919.29 U5.A1@4563.13,919.29
  Bottom Layer w6: v1(1866.81,641.2) 1896.81,611.2 R186.1@1941.49,611.2 ; v1(1912.4,1085.54) 1914.11,1083.82 1931.4,1083.82 1957.4,1057.82 R67.1@1957.4,1057.03
  Bottom Layer w8: U13.5@2268.5,609.06 v1(2298.5,609.06)
  Bottom Layer w9: U27.9@1868.71,1241.38 1869.13,1240.96 1882.94,1240.96 1892.52,1231.38 v1(1893.71,1231.38) ; U30.13@1887.4,1075.54 1887.48,1075.62 1901.49,1075.62 1911.4,1085.54 v1(1912.4,1085.54)
SDA0: R92.1 U26.1 U44.4 U45.4 | length 1622.4
  L16 PWR/SIG w5: v1(1290.31,1463.86) 1288.22,1463.86 1268.5,1444.14 1268.5,1405.3 1197.03,1333.83 1197.03,1265.7 1132.45,1201.11 1132.45,1088.73 1120.35,1076.64 1120.35,967.34 1132.45,955.24 1132.45,935.89 1197.59,870.75 1197.59,800.93 1270.98,727.53 1294.06,727.53 1307.99,713.6 1307.99,667.54 1342.53,633 1693.32,633 1714.56,654.24 v1(1714.56,678.81)
  Bottom Layer w5: U44.4@1190.31,1463.86 1190.65,1464.19 1190.65,1483.25 1197.33,1489.93 1282.69,1489.93 1287.02,1485.61 1287.02,1467.15 v1(1290.31,1463.86)
  Bottom Layer w8: R92.1@1707.48,676.8 1714.55,676.8 1716.86,679.08 1724.17,679.08 1741.51,696.42 1757.1,696.42 U26.1@1757.48,696.8 ; R92.1@1707.48,678.8 R92.1@1714.55,678.8
SDA1: R94.1 U26.3 U50.4 U51.4 | length 1219.7
  L16 PWR/SIG w5: v1(1290.31,1163.86) 1290.31,1143.76 1188.03,1041.48 1188.03,893.04 1206.59,874.48 1206.59,810.14 1256.86,759.87 1296.08,759.87 1352.28,703.66 1429.93,703.66 1430,703.73 1495.67,703.73 1495.74,703.66 1577.94,703.66 1627.36,654.24 1675.72,654.24 1694.28,672.8 1694.28,711.9 v1(1714.56,732.18)
  Bottom Layer w5: U50.4@1190.31,1163.86 1190.65,1164.19 1190.65,1183.25 1197.33,1189.93 1282.69,1189.93 1287.02,1185.61 1287.02,1167.15 v1(1290.31,1163.86)
  Bottom Layer w8: v1(1714.56,732.18) 1737.49,732.15 1741.51,736.17 U26.3@1757.48,736.17
SDA2: R96.1 U26.5 U38.4 | length 2455.8
  Top Layer w10: v1(234.6,1312.56) U38.4@234.6,1342.56
  L16 PWR/SIG w5: v1(234.6,1312.56) 236.49,1310.66 247.45,1310.66 262.8,1295.32 262.8,1156.22 184.65,1078.07 184.65,952.56 256.45,880.76 256.45,785.65 279.29,762.8 474.24,762.8 496.44,785 740.46,785 887.51,637.95 1075.33,637.95 1104.28,609 1698.05,609 1769.12,680.07 1769.12,732.63 1714.56,787.19 v1(1714.56,787.55)
  Bottom Layer w8: R96.1@1707.48,787.54 1714.55,787.54 1716.86,785.25 1725.18,785.25 1734.9,775.54 U26.5@1757.48,775.54
SDA3: R98.1 U26.7 U47.4 U48.4 | length 720.3
  L16 PWR/SIG w5: v1(1290.31,863.86) 1324.86,898.41 1633.31,898.41 1669.28,862.43 1752.37,862.43 v1(1775.08,839.72)
  Bottom Layer w5: U47.4@1190.31,863.86 1190.65,864.19 1190.65,883.25 1197.33,889.93 1282.69,889.93 1287.02,885.61 1287.02,867.15 v1(1290.31,863.86)
  Bottom Layer w8: v1(1775.08,839.72) R98.1@1775.07,870.81 ; v1(1775.08,839.72) 1775.08,835.88 1783.07,827.9 U26.7@1783.07,820.81
SDA4: R100.1 U26.10 U41.4 U42.4 U60.A1 | length 2045.2
  Top Layer w8: v1(748.89,1780.89) 748.89,1777.64 756.45,1770.08 756.45,1757.93 U60.A1@756.65,1757.72
  L16 PWR/SIG w5: v1(1290.31,1763.86) 1290.31,1761.23 1392.34,1659.2 1392.34,1169.19 1681.1,880.43 1814.82,880.43 1829.46,865.8 1840.07,865.8 v1(1842.14,863.72)
  L10 SIGNAL w5: v1(748.89,1780.89) 765.92,1763.86 765.92,1740.01 801.86,1704.07 899.9,1704.07 959.69,1763.86 v1(1290.31,1763.86)
  Bottom Layer w5: U41.4@1190.31,1763.86 1190.65,1764.19 1190.65,1783.25 1197.33,1789.93 1282.69,1789.93 1287.02,1785.61 1287.02,1767.15 v1(1290.31,1763.86)
  Bottom Layer w8: U26.10@1842.12,820.81 v1(1842.14,863.72) ; v1(1842.14,863.72) R100.1@1842.12,870.81
SDA_FMC: J29.C31 U9.7 | length 4484.5
  L16 PWR/SIG w5: v1(2029.93,516.36) 2056.74,516.36 2146.68,426.41 2146.68,358.14 2192.03,312.8 3885.72,312.8 3896.18,302.34 4008.1,302.34 4034.33,276.11 4071.19,276.11 4097.41,302.34 4179.99,302.34 4196.56,285.77 4427.91,285.77 4599.63,457.5 4631.45,457.5 4641.14,447.81 4691.98,447.81 4701.06,456.89 4701.06,489.99 4776.07,565 4826.62,565 5321.65,565 5559.65,803 5932.15,803 v1(5961.42,832.27)
  Bottom Layer w6: v1(2029.93,516.36) 2028.12,518.17 2028.12,530.48 2022.93,535.68 2022.93,554.36 2059.88,591.31 2059.88,607.34 2051.76,615.46 2031.8,615.46 U9.7@2030.85,616.41
SDA_FMC_3p3V: R186.2 U9.2 | length 34
  Bottom Layer w6: R186.2@1963.54,611.2 1964.33,611.2 1969.53,616.41 U9.2@1995.42,616.41
SDI_FMC_VADJ: J29.G13 U15.3 U18.3 | length 5703.3
  L16 PWR/SIG w5: v1(1275.01,2231.5) 1329.38,2285.87 1329.38,2339.25 v1(1337.89,2347.76) 1366.88,2376.74 1366.88,2408.59 1307.47,2468 1200.61,2468 1155.6,2513 1155.6,2576.12 1214.52,2635.04 2530.98,2635.04 2548.97,2617.05 2548.97,2459.63 2588.6,2420 3317.8,2420 3389.8,2348 3886.65,2348 3935.81,2298.84 3976.45,2298.84 4009.05,2266.25 4441.53,2266.25 4526.3,2181.47 4629.28,2181.47 4666.08,2144.67 5220.87,2144.67 5354.68,2010.87 5606.91,1758.63 5735.05,1758.63 v1(5761.42,1732.27)
  Bottom Layer w8: U18.3@1270.01,2196.5 1270.01,2223.25 1275.01,2228.25 v1(1275.01,2231.5) ; U15.3@1302.89,2352.76 U15.3@1304.86,2352.76 1329.64,2352.76 1334.64,2347.76 v1(1337.89,2347.76)
SDI_LMK_USB: J28.35 U6.9 | length 820.7
  Top Layer w8: J28.35@504.68,2395 v1(504.69,2455)
  L16 PWR/SIG w5: v1(504.69,2455) 523.83,2455 655.33,2323.5 660.94,2323.5 695.4,2289.04 695.4,2263.7 708.47,2250.63 1068.62,2250.63 1083.36,2265.37 v1(1083.36,2305.63)
  Bottom Layer w8: U6.9@1068.36,2335.63 1068.36,2320.63 v1(1083.36,2305.63)
SDIOr_ADC: J22.4 J23.2 J41.7 R60.2 U1.L3 | length 5299.8
  Top Layer w5: J41.7@1832.62,2536.06 1830.97,2534.41 1830.97,2507.89 1806.25,2483.17 1806.25,2351.36 1869.86,2287.75 R60.2@1925.39,2287.75 1925.39,2207.73 J23.2@1957.76,2175.36
  L5 PWR/SIG w4: J41.7@1832.62,2536.06 1857.38,2560.82 1857.38,2601.05 1881.52,2625.19 2435.62,2625.19 2482.56,2578.25 v1(2482.56,2497.89)
  L12 SIGNAL w4: v1(2482.56,2497.89) 2530.84,2449.61 2530.84,2354.97 2533.18,2352.62 2930.48,2352.62 2980.67,2302.44 2980.67,2151.54 3281.94,1850.27 3806.64,1850.27 3825.9,1869.53 3825.9,1890.59 3876.58,1941.27 3937.4,1941.27 3995.61,1883.06 3995.61,1729.05 4085.44,1639.22 4085.44,1614.81 4141.26,1558.99 4155.78,1558.99 4182.12,1532.65 4182.12,1492.12 4283.96,1390.28 4322.27,1351.97 4359.29,1351.97 4402.07,1309.19 4402.07,1296.68 4421.13,1277.62 4495.11,1277.62 4559.76,1342.27 4651.93,1342.27 4658.52,1348.85 4658.52,1522.17 4667.84,1531.5 4721.26,1531.5 v1(4737.01,1547.24)
  Bottom Layer w5: J22.4@1363.54,1990.01 1522.3,1990.01 1536.07,1976.25 1758.64,1976.25 1772.41,1990.01 J23.2@1957.76,2175.36
SDIOr_ADC_FMC_GPIOVDD: U7.11 U18.9 | length 420.2
  Top Layer w5: v1(1070.49,1956.38) 1070.78,1956.38 1088.41,1938.74 1202.7,1938.74 1300.76,2036.8 v1(1300.76,2105.47)
  Bottom Layer w8: v1(1070.49,1956.38) 1070.49,1959.63 1075.49,1964.63 U7.11@1075.49,1991.38 ; U18.9@1285.76,2135.47 1285.76,2120.47 v1(1300.76,2105.47)
SDIOr_ADC_FT: J28.10 U23.3 | length 82.9
  Top Layer w8: J28.10@760.59,2169.41 760.67,2169.33 760.67,2124.72 772.4,2112.99 U23.3@772.4,2091.38
SDIOr_ADC_USB_GPIOVDD: U7.12 U23.10 | length 394
  Top Layer w8: v1(767.4,1998.39) 767.4,2001.63 772.4,2006.63 U23.10@772.4,2028.39
  L16 PWR/SIG w5: v1(767.4,1998.39) 767.4,1960.87 780.28,1947.99 1031.35,1947.99 v1(1044.74,1961.38)
  Bottom Layer w8: v1(1044.74,1961.38) 1059.74,1976.38 U7.12@1059.74,1991.38
SDIOr_FPGA_FT: J28.46 U16.3 | length 82.9
  Top Layer w8: J28.46@406.18,2169.49 J28.46@406.26,2169.41 406.26,2124.81 417.99,2113.08 U16.3@417.99,2091.46
SDIOr_FPGA_VADJ: J29.C14 U16.10 | length 9630.8
  Top Layer w8: v1(413.07,1998.39) 413.07,2001.63 418.07,2006.63 U16.10@418.07,2028.39
  L16 PWR/SIG w5: v1(413.07,1998.39) 411.79,1998.39 402.64,1989.24 103.43,1989.24 71.19,1956.99 71.19,1689.64 54.7,1673.16 54.7,1421.86 71.19,1405.37 71.19,791.58 135.96,726.8 490.08,726.8 512.27,749 725.55,749 983.83,490.72 1320.72,490.72 1389.84,559.84 1907.71,559.84 1950.36,602.49 1950.36,879.3 2050.53,979.47 2104.55,979.47 2145.26,938.77 2145.26,787.84 2066.21,708.8 2066.21,545.07 2159.28,452 2221.94,452 2271,402.94 2271,353.73 2284.93,339.8 3886.42,339.8 3984.23,437.61 4082.9,437.61 4155.26,365.26 4194.73,365.26 4247.22,312.77 4408.67,312.77 4587.31,491.4 4664.29,491.4 4764.89,592 5007.36,592 5065.03,649.67 5242.63,649.67 5555.71,962.75 5868.56,962.75 5939.3,1033.48 5939.3,1660.15 v1(5961.42,1682.27)
SDIOr_LMK: J21.4 R56.2 U2.5 U6.10 | length 4225.9
  L16 PWR/SIG w5: v1(1057.61,2302.25) 1057.61,2303.22 1087.11,2332.72 1120.59,2332.72 1145.72,2357.85 1145.72,2417.44 1157.16,2428.88 1157.16,2469.97 1137.67,2489.45 1125.3,2501.82 1125.3,2585.3 1202.04,2662.04 3317.63,2662.04 3343.65,2636.02 3343.65,2432.33 3399.1,2376.88 3697.33,2376.88 3954.18,2633.73 4189.21,2633.73 4199.4,2623.53 4233.49,2623.53 J21.4@4260.66,2650.7
  L10 SIGNAL w5: J21.4@4260.66,2650.7 4287.42,2623.94 v1(4287.42,2432.56)
  Bottom Layer w5: J21.4@4260.66,2650.7 4260.66,2600.89 4271.82,2589.72 R56.2@4271.82,2588.93 ; U2.5@4267.42,2432.56 v1(4287.42,2432.56)
  Bottom Layer w8: v1@1052.61,2308.88 U6.10@1052.61,2335.63
SDIOr_LMK_FMC_3p3V: U6.11 U15.9 | length 327
  Bottom Layer w8: U6.11@1036.86,2335.63 1036.86,2308.88 1031.86,2303.88 1031.86,2260.63 1041.86,2250.63 1140.49,2250.63 1226.86,2337.01 U15.9@1241.86,2337.01
SDIOw_ADC: J13.13 J23.3 R187.2 U1.L15 | length 6588.2
  L16 PWR/SIG w5: J13.13@1282.61,2536.06 1282.61,2531.04 1309.65,2504 1332.59,2504 1476.58,2360.01 1476.58,2344.34 1581.81,2239.11 1685.18,2239.11 1755.96,2168.33 1798.96,2168.33 1829.36,2137.93 1829.36,2089.82 1801.81,2062.28 1801.81,1961.71 1824.79,1938.73 1824.79,1850.47 1919.4,1755.86 1970.39,1755.86 1988.94,1737.31 1988.94,1347.59 2065.47,1271.06 2481.6,1271.06 2524.43,1313.89 2888.88,1313.89 2997.17,1205.61 2997.17,1162.26 3011.38,1148.05 3048.99,1148.05 3136.75,1060.29 3417.39,1060.29 3515.39,1158.29 3536.14,1158.29 3551.64,1173.79 4241.54,1173.79 4247.92,1180.17 4568.49,1180.17 4573.11,1184.79 4721.51,1184.79 v1(4737.01,1169.29)
  L10 SIGNAL w5: v1(1160.44,2110.63) 1199.99,2110.63 1214,2124.64 1214,2210.01 ; J13.13@1282.61,2536.06 1282.61,2509.64 1207.35,2434.39 1207.35,2216.65 1214,2210.01 ; v1(1512.85,2012.2) 1512.85,2051.79 1350.52,2214.12 1327.96,2214.12 1323.85,2210.01 1214,2210.01
  Bottom Layer w5: v1(1160.44,2110.63) 1160.44,2103.71 R187.2@1160.6,2103.54 ; v1(1512.85,2012.2) 1539.8,1985.25 1749.71,1985.25 1917.38,2152.91 1917.38,2267.31 1968.88,2318.81 2070.03,2318.81 2103.94,2284.9 2103.94,2121.55 J23.3@2057.76,2075.36
SDIOw_ADC_FMC_GPIOVDD: U7.4 U18.10 | length 243.6
  Top Layer w5: v1(1121.98,2082.4) 1169.46,2082.4 1211.86,2124.81 1250.68,2124.81 v1(1275.01,2100.47)
  Bottom Layer w8: U7.4@1106.98,2052.4 U7.4@1106.98,2054.37 1106.98,2067.4 v1(1121.98,2082.4) ; v1@1270.01,2108.72 U18.10@1270.01,2135.47
SDIOw_ADC_FT: J28.6 U23.2 | length 82.9
  Top Layer w8: U23.2@788.15,2091.38 788.15,2113.43 799.45,2124.72 799.45,2168.9 J28.6@799.96,2169.41
SDIOw_ADC_USB_GPIOVDD: U7.3 U23.11 | length 487.2
  Top Layer w8: U23.11@788.15,2028.39 788.15,2006.63 793.15,2001.63 v1(793.15,1998.39)
  L16 PWR/SIG w5: v1(793.15,1998.39) 830.16,1961.38 992.54,1961.38 1018.65,1987.48 1055.51,1987.48 1081.62,2013.58 1081.62,2028.68 1106.48,2053.55 1106.48,2084.47 1103.55,2087.4 v1(1096.23,2087.4)
  Bottom Layer w8: U7.3@1091.23,2052.4 U7.3@1091.23,2054.37 1091.23,2079.15 1096.23,2084.15 v1(1096.23,2087.4)
SDIOw_FPGA_FT: J28.42 U16.2 | length 82.9
  Top Layer w8: U16.2@433.74,2091.46 433.74,2113.51 445.04,2124.81 445.04,2168.98 J28.42@445.55,2169.49
SDIOw_FPGA_VADJ: J29.C11 U16.11 | length 9608.3
  Top Layer w8: U16.11@433.82,2028.39 433.82,2006.63 438.82,2001.63 v1(438.82,1998.39)
  L16 PWR/SIG w5: v1(438.82,1998.39) 436.41,1998.39 398.87,1960.85 389.03,1960.85 359.81,1931.63 211.71,1931.63 112.78,1832.7 98.74,1832.7 80.19,1814.15 80.19,1688.84 105.38,1663.64 105.38,1427.76 80.19,1402.56 80.19,795.31 139.69,735.8 486.35,735.8 508.54,758 729.28,758 987.56,499.72 1316.99,499.72 1386.11,568.84 1903.98,568.84 1941.36,606.22 1941.36,883.03 2046.8,988.47 2109.68,988.47 2180.07,918.08 2180.07,809.93 2075.21,705.07 2075.21,548.8 2163.01,461 3868.99,461 3883.38,446.61 4086.63,446.61 4158.98,374.26 4198.46,374.26 4250.95,321.77 4403.69,321.77 4626.42,544.5 4651.1,544.5 4707.6,601 4970.4,601 5091.78,722.38 5279.61,722.38 5555.85,998.62 5863.62,998.62 5895.92,1030.92 5895.92,1038.69 5905,1047.77 5912.77,1047.77 5930.3,1065.3 5930.3,1677.57 5976.92,1724.19 5976.92,1788.69 5961.42,1804.19 v1(5961.42,1832.27)
SDIOw_LMK: J21.3 U2.20 U6.7 | length 4214.8
  L16 PWR/SIG w5: v1(1116.3,2360.79) 1097.57,2360.79 1077.75,2380.61 1077.75,2582.75 1175.04,2680.04 4281.32,2680.04 J21.3@4310.66,2650.7
  L10 SIGNAL w5: v1(4182.77,2170.43) 4182.77,2148.2 4198.05,2132.92 4228.54,2132.92 4242.63,2147.01 4250.22,2147.01 4268.83,2165.62 4268.83,2372.74 4308.98,2412.89 4308.98,2649.02 J21.3@4310.66,2650.7
  Bottom Layer w8: U6.7@1091.98,2359.25 v1@1121.98,2359.25
  Bottom Layer w10: v1(4182.77,2170.43) U2.20@4182.77,2190.43
SDIOw_LMK_FMC_3p3V: U6.8 U15.10 | length 160.6
  Bottom Layer w8: U6.8@1091.98,2343.5 1106.98,2343.5 1113.9,2336.59 1113.9,2335.8 1198.16,2335.8 1215.11,2352.76 U15.10@1241.86,2352.76
SDO_FMC_VADJ: J29.G15 U17.4 U20.4 | length 5691.2
  L16 PWR/SIG w5: v1(1420,2245) 1420,2271.9 1414.5,2277.4 1414.5,2373.7 1311.2,2477 1204.34,2477 1164.6,2516.73 1164.6,2572.39 1218.24,2626.04 2522.25,2626.04 2539.97,2608.31 2539.97,2455.91 2584.87,2411 3314.07,2411 3386.07,2339 3882.92,2339 3899.66,2322.27 3899.66,2288.56 3930.97,2257.25 4437.8,2257.25 4522.57,2172.47 4625.55,2172.47 4662.35,2135.67 5217.14,2135.67 5605.05,1747.77 5617.84,1747.77 5640.86,1724.75 5640.86,1680.91 5673.21,1648.56 5726.69,1648.56 5742.98,1632.27 v1(5761.42,1632.27)
  Bottom Layer w8: U20.4@1420,2230 v1(1420,2245) U17.4@1420,2260
SDO_LMK_USB: J28.27 U6.12 | length 605.2
  Top Layer w8: J28.27@583.43,2395 584,2395.57 584,2445.57 v1(603.43,2465)
  L16 PWR/SIG w5: v1(603.43,2465) 603.43,2427.48 725.28,2305.63 v1(1006.12,2305.63)
  Bottom Layer w8: v1(1006.12,2305.63) 1021.12,2320.63 U6.12@1021.12,2335.63
SEN_ADC: J13.15 J22.5 U1.J16 U7.7 | length 5847.7
  L16 PWR/SIG w4: 4781.46,1083.36 4783.55,1085.44 4783.55,1113.18
  L16 PWR/SIG w5: v1(1160.6,2015) 1235.59,1940.01 1413.54,1940.01 1430.14,1956.61 ; J13.15@1232.61,2536.06 1236.03,2536.06 1277.09,2495 1318.65,2495 1462.87,2350.78 1462.87,2258.42 1485.87,2235.42 1485.87,2177.87 1439.68,2131.68 1405.5,2097.5 1405.5,2004.27 1430.14,1979.63 1430.14,1956.61 ; 4781.46,1083.36 4559.66,1083.36 4498.28,1021.98 4329.5,1021.98 4315.4,1036.08 4265.66,1036.08 4201.46,1100.28 3838.52,1100.28 3827.81,1089.57 3748.95,1089.57 3736.27,1102.26 3683.69,1102.26 3664.22,1082.79 3555.74,1082.79 3536.27,1102.26 3499.85,1102.26 3439.89,1042.29 3072.7,1042.29 2979.17,1135.82 2979.17,1198.15 2881.43,1295.89 2537.26,1295.89 2511.14,1269.77 2511.14,984.09 2453.74,926.69 2399.35,926.69 2370.13,897.47 2317.14,897.47 2146.65,1067.96 2085.54,1067.96 1925.02,1228.48 1925.02,1310.22 1897.26,1337.98 1813.43,1337.98 1773.61,1377.79 1773.61,1844.83 1661.84,1956.61 1430.14,1956.61 ; 4783.55,1113.18 4783.55,1121.34 v1(4800,1137.8)
  Bottom Layer w8: U7.7@1130.6,2015 v1(1160.6,2015)
SEN_ADC_FMC_GPIOVDD: U7.8 U18.11 | length 247.2
  Top Layer w5: v1(1155.6,1989.25) 1207.64,1989.25 1249.26,2030.88 v1(1249.26,2100.47)
  Bottom Layer w8: U7.8@1130.6,1999.25 1145.6,1999.25 1152.52,1992.34 1152.52,1991.55 1154.82,1989.25 v1(1155.6,1989.25) ; v1(1249.26,2100.47) 1249.26,2103.72 1254.26,2108.72 U18.11@1254.26,2135.47
SEN_ADC_FMC_VADJ: J29.G18 U18.2 U20.1 | length 6133.7
  L16 PWR/SIG w5: v1(1249.26,2231.5) 1249.57,2231.19 1249.57,2217.05 1261.58,2205.04 1318.88,2205.04 1327.96,2214.12 1340.8,2214.12 1385.24,2169.68 1452.67,2169.68 v1(1469.37,2186.38) 1469.37,2208.08 1453.87,2223.58 1453.87,2347.05 1314.92,2486 1208.61,2486 1177.58,2517.03 1177.58,2572.64 1221.98,2617.04 2514.93,2617.04 2528.73,2603.24 2528.73,2454.42 2581.15,2402 3310.34,2402 3382.34,2330 3810.62,2330 3892.38,2248.25 3903.38,2248.25 4434.07,2248.25 4518.85,2163.47 4621.82,2163.47 4658.62,2126.67 5213.41,2126.67 5568.27,1771.82 5568.27,1747.33 5627.94,1687.67 5627.94,1643.83 5661.53,1610.24 5711.14,1610.24 5744.92,1576.46 5744.92,1526.85 5761.42,1510.35 v1(5761.42,1482.27)
  Bottom Layer w8: U18.2@1254.26,2196.5 v1@1254.26,2223.25 ; U20.1@1459.37,2206.38 1459.37,2197.06 1469.37,2187.06 v1(1469.37,2186.38)
SEN_ADC_FT: J28.12 U23.4 | length 84.6
  Top Layer w8: J28.12@740.91,2169.41 740.99,2169.33 740.99,2118.34 756.65,2102.68 U23.4@756.65,2091.38
SEN_ADC_USB_GPIOVDD: U7.9 U23.9 | length 684.9
  Top Layer w8: v1(741.65,2008.39) 743.95,2010.68 753.1,2010.68 756.65,2014.24 U23.9@756.65,2028.39
  L16 PWR/SIG w5: v1(741.65,2008.39) 741.65,1871.86 790.28,1823.23 1022.97,1823.23 1121.98,1922.24 v1(1121.98,1961.38)
  Bottom Layer w8: U7.9@1106.98,1991.38 1106.98,1976.38 v1(1121.98,1961.38)
SEN_FPGA_FT: J28.48 U16.4 | length 84.6
  Top Layer w8: J28.48@386.49,2169.49 J28.48@386.57,2169.41 386.57,2118.43 402.24,2102.76 U16.4@402.24,2091.46
SEN_FPGA_VADJ: J29.C15 U16.9 | length 9646.7
  Top Layer w8: v1(387.32,2008.39) 389.62,2010.68 398.76,2010.68 402.32,2014.24 U16.9@402.32,2028.39
  L16 PWR/SIG w5: v1(387.32,2008.39) 100.17,2008.39 62.19,1970.4 62.19,1698.76 45.7,1682.28 45.7,1412.74 62.19,1396.26 62.19,787.85 132.23,717.8 493.8,717.8 516,740 721.82,740 980.11,481.72 1324.45,481.72 1393.57,550.84 1911.44,550.84 1954.63,594.03 1959.36,598.76 1959.36,875.57 2054.26,970.47 2100.82,970.47 2136.26,935.04 2136.26,791.57 2057.21,712.52 2057.21,541.34 2155.55,443 2218.22,443 2262,399.22 2262,350 2281.2,330.8 3890.14,330.8 3987.96,428.61 4079.17,428.61 4151.53,356.26 4191,356.26 4243.49,303.77 4412.4,303.77 4591.03,482.4 4668.02,482.4 4768.62,583 5011.09,583 5068.76,640.67 5246.36,640.67 5558.49,952.8 5907.91,952.8 5990,1034.88 5990,1603.69 v1(5961.42,1632.27)
SEQ_DVDD_09: R227.1 U63.6 U64.1 | length 995.8
  Top Layer w5: v3(82.39,1500.59) 113.09,1531.29 388.89,1531.29 432.6,1575 621.27,1575 641.82,1595.55 829.22,1595.55 v3(845.81,1578.95)
  Bottom Layer w8: v3(845.81,1578.95) 861.91,1595.04 U63.6@900.59,1595.04
  Bottom Layer w10: v3(82.39,1500.59) 114.14,1500.59 120,1506.45 120,1575.48 116.53,1578.95 116.53,1580.92 111.69,1585.76 R227.1@109.72,1585.76
SEQ_VDD_12: R231.1 U63.5 U66.1 | length 200.6
  Bottom Layer w8: U63.5@937.99,1595.04 937.99,1540.36 957.53,1520.81 R231.1@984.58,1520.81 984.58,1542.86 992.19,1550.47 U66.1@1050.63,1550.47
SEQ_VDD_18: R236.1 U63.4 U68.2 | length 492.5
  Top Layer w5: v3(975.39,1595.04) 961.49,1581.14 961.49,1273.89 v3(1014.58,1220.81)
  Bottom Layer w8: v3(1014.58,1220.81) 1015.96,1219.43 1071.53,1219.43 1076.22,1224.12 U68.2@1076.22,1250.47
SMA_JESDCLKIN_N: C99.1 R192.1 R196.2 U56.6 | length 95.2
  Bottom Layer w8: 4442.16,683.68 4442.16,692.95 4442.05,693.05 4442.05,693.14 U56.6@4447.53,698.62
  Bottom Layer w12: C99.1@4421.93,614.1 4434.24,626.41 4442.16,634.33 4442.16,639.46 4442.16,683.68
SMA_JESDCLKIN_P: C75.1 R191.1 R195.2 U56.7 | length 95.2
  Bottom Layer w8: 4421.45,704.39 4430.72,704.39 4430.82,704.28 4430.91,704.28 U56.7@4436.39,709.76
  Bottom Layer w12: C75.1@4351.88,684.16 4364.19,696.47 4372.1,704.39 4374.41,704.39 4377.88,704.39 4421.45,704.39
Switcher_2p3V: C223.2 C224.2 C225.2 C226.2 FB4.1 FB5.1 R126.2 U39.13 U39.14 U39.15 U39.16 U39.17 U39.18 U39.19 U39.20 U39.21 U39.22 U39.23 U39.24 U39.25 U39.26 | length 608.1
  L16 PWR/SIG w5: v1(209.01,983.07) 290.74,1064.8 349.28,1064.8 781.22,1064.8 v1(782.67,1066.26)
SYSREF_SMA: C53.2 J11.1 R76.2 | length 510.6
  Bottom Layer w12: v1(3534.82,2534.21) 3707.86,2534.21 3795,2447.07 3795,2316.12 3817.86,2293.26 R76.2@3838.91,2293.26 C53.2@3868.91,2293.26
TDI_FMC: J29.D30 R84.2 | length 14
  Top Layer w8: R84.2@5911.42,868.29 v1(5911.42,882.27)
TDO_FMC: J29.D31 R84.1 | length 14
  Top Layer w8: v1(5911.42,832.27) R84.1@5911.42,846.24
TSTAMP_N: R44.1 U1.P7 | length 2465
  Top Layer w7.4: R44.1@2664.16,2114.88 2664.94,2114.88 2667.54,2112.28 2667.54,2110.89 2671.88,2106.56 2686.35,2106.56 2693.65,2113.86 v1(2696.98,2113.86)
  L10 SIGNAL w3.5: v1(2696.98,2113.86) 2695.31,2113.86 2686.81,2105.36 2661.58,2105.36 2647.34,2091.12 2634.53,2078.3 2634.53,2019.22 2637.46,2016.29 2703.74,1950 3103.97,1950 3229.3,1824.67 3282.24,1771.73 3299.7,1754.27 3784.06,1754.27 3799.56,1738.77 3799.56,1727.84 3826.18,1701.22 3878.25,1701.22 3887.2,1692.27 3955.77,1623.7 3967.45,1612.02 4196.79,1612.02 4208.92,1624.15 4265.77,1624.15 4342.07,1624.15 4350.41,1615.81 4407.83,1558.39 4454.36,1558.39 4458.18,1554.58 4469.06,1543.7 4518.51,1494.25 4518.51,1466.06 4531.9,1452.67 4531.9,1452.61 4546.99,1437.52
  L10 SIGNAL w4: 4546.99,1437.52 4626.26,1437.52 v1(4642.52,1421.26)
TSTAMP_P: R43.1 U1.N7 | length 2486.6
  Top Layer w7.4: R43.1@2664.16,2085.83 2664.94,2085.83 2667.54,2088.43 2667.54,2089.82 2671.88,2094.16 2686.35,2094.16 2693.65,2086.86 v1(2696.98,2086.86)
  L10 SIGNAL w3.5: v1(2696.98,2086.86) 2695.31,2086.86 2686.81,2095.36 2665.73,2095.36 2651.48,2081.12 2644.53,2074.16 2644.53,2023.36 2661.58,2006.3 2707.89,1960 3108.11,1960 3239.3,1828.81 3286.38,1781.73 3303.84,1764.27 3788.2,1764.27 3809.56,1742.91 3809.56,1731.99 3830.32,1711.22 3882.39,1711.22 3894.27,1699.34 3971.59,1622.02 4192.65,1622.02 4204.78,1634.15 4346.22,1634.15 4357.48,1622.88 4411.97,1568.39 4458.51,1568.39 4476.13,1550.77 4528.51,1498.39 4528.51,1470.2 4538.94,1459.77 4539,1459.77 4546.99,1467.76
  L10 SIGNAL w4: 4546.99,1467.76 4648.73,1467.76 4658.27,1458.22 4658.27,1447.29 4671.84,1433.71 4671.84,1423.43 v1(4674.02,1421.26)
USB_SCL: J28.28 R70.1 U12.1 | length 89.8
  Top Layer w8: J28.28@583.43,2169.41 583.43,2124.72 604.5,2103.65 604.5,2089.47 604.43,2089.41 U12.1@603.43,2089.41
  other v1: 604.65,2108.39
USB_SDAr: J28.34 R82.1 | length 122.6
  Top Layer w8: R82.1@521.32,2048.09 521.32,2048.87 524.37,2051.93 J28.34@524.37,2169.41
USB_SDAw: J28.30 TP8.1 U14.1 | length 622
  Top Layer w8: U14.1@543.74,2089.41 542.73,2089.41 542.67,2089.47 542.67,2103.65 563.74,2124.72 J28.30@563.74,2169.41 v1(563.74,2229.41)
  Bottom Layer w8: TP8.1@556.26,2635 479.51,2558.25 479.51,2373.42 563.74,2289.19 v1(563.74,2229.41)
V-SENSE-MUX: U30.8 U57.8@1684.51,959.19 | length 208.8
  Top Layer w12: U57.8@1684.51,959.19 1684.81,959.5 1684.81,979.86 v1(1685.12,980.17)
  Bottom Layer w6: v1(1685.12,980.17) 1720.77,980.17 1740.03,999.42 1740.03,1014.26 1730.16,1024.12 1730.16,1067.89 1740.12,1077.85 1766.83,1077.85 1769.14,1075.54 U30.8@1777.16,1075.54
V-SENSE-MUX-A0: U57.1 U58.2 | length 81.9
  Top Layer w5: U58.2@1585.08,971.72 1586.02,970.78 1598.27,970.78 1636.62,932.43 1644.2,932.43 1645.14,931.49 U57.1@1645.14,926.32
V-SENSE-MUX-A1: U57.10 U58.3 | length 71.8
  Top Layer w5: U58.3@1585.08,987.46 1604.06,987.46 1632.33,959.19 U57.10@1645.14,959.19
VADJ: J29.E39 J29.F40 J29.G39 J29.H40 R202.1 SW6.3
  other v1: 5711.42,382.27 5811.42,382.27 5761.42,432.27 5861.42,432.27
  other v3: 3970.08,463.12 3955.94,477.26 3984.22,477.26
pads on no net: FID1.1 FID2.1 FID3.1 H2. H4. J28.4@153.9,882.21 J28.4@953.9,882.2 J28.MH1 J28.MH2 J29. J43. J44. Q1.0 SH-J19.0 SH-J20.0 SH-J24.0 SH-J25.0 SH-J26.0 SH-J27.0 SH-J30.0 SH-J34.0 SH-J38.0 SH-J39.0 SH-J40.0 SH-J45.0 U57.3@1684.51,926.32 U57.8@1684.51,959.19 U59.3@1544.55,1296.99 U59.8@1544.55,1264.12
